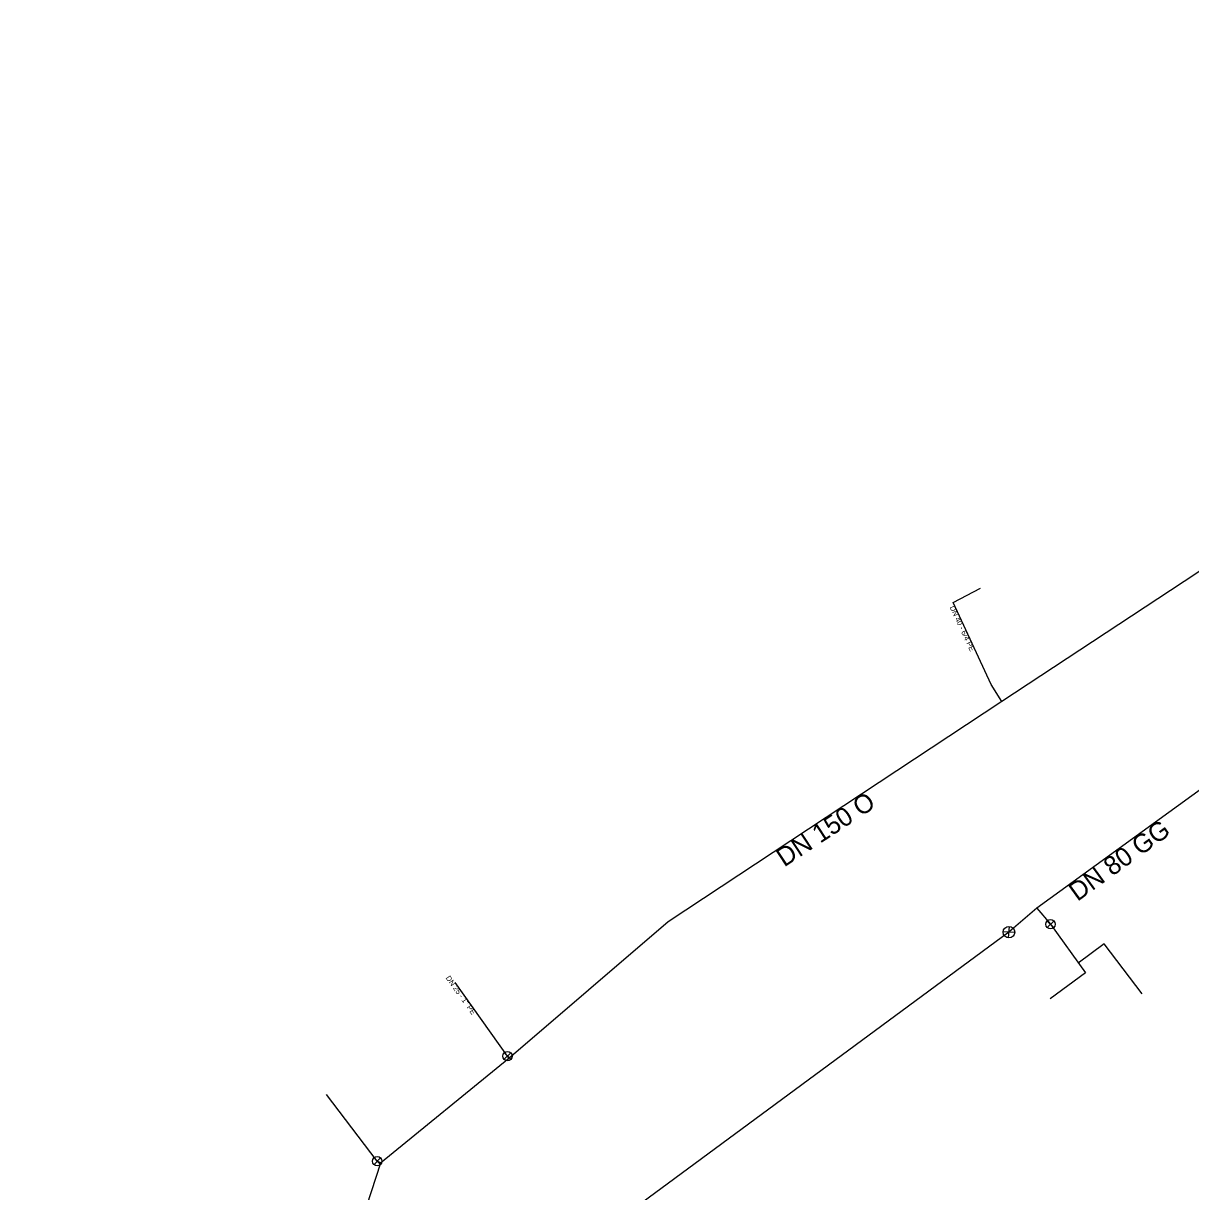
# Model space of a CAD drawing. Extents: x -451501 to -451094, y -1102108 to -1101623.
# Drawn here: x -451475.7 to -451375.4, y -1101738.2 to -1101637.8 of the extents above; entities that cross this region are included whole.
import ezdxf

# ---------------------------------------------------------------- set-up
doc = ezdxf.new("R2010")
doc.units = 0
for name, color, linetype in [('_pripojka_prevzato_z_dokumentace_', 7, 'Continuous'), ('_pripojka_priblizne_', 7, 'Continuous'), ('_voda_smvak_prevzato_z_dokumentace_', 7, 'Continuous'), ('Default', 7, 'Continuous'), ('MoLevel 27', 7, 'Continuous'), ('MoLevel 32', 7, 'Continuous'), ('MoLevel 46', 7, 'Continuous'), ('MoLevel 53', 7, 'Continuous'), ('MoLevel 55', 7, 'Continuous')]:
    doc.layers.add(name, color=color, linetype=linetype)

# ---------------------------------------------------------------- blocks, each defined once
blk = doc.blocks.new('_uzaver_')
at = {"layer": 'Default'}
for p, q in [((-0.000035, -0.000035), (0.000035, 0.000035)), ((0.000035, -0.000035), (-0.000035, 0.000035))]:
    blk.add_line(p, q, dxfattribs=at)
for radius in [0.00005, 0.0000025]:
    blk.add_circle((0, 0), radius, dxfattribs=at)
blk = doc.blocks.new('_uzaver_pripojka_')
at = {"layer": 'Default'}
for p, q in [((-0.000035, -0.000035), (0.000035, 0.000035)), ((0.000035, -0.000035), (-0.000035, 0.000035))]:
    blk.add_line(p, q, dxfattribs=at)
for radius in [0.00005, 0.0000025]:
    blk.add_circle((0, 0), radius, dxfattribs=at)

msp = doc.modelspace()

# ---------------------------------------------------------------- linework, layer by layer
at = {"layer": '_pripojka_prevzato_z_dokumentace_'}
for points in [[(-451388.63, -1101713.82), (-451387.47, -1101715.2), (-451384.47, -1101719.38), (-451387.5, -1101721.61)], [(-451434, -1101726.73), (-451434.13, -1101726.53), (-451438.63, -1101720.2)], [(-451445.03, -1101735.74), (-451445.32, -1101735.57), (-451449.67, -1101729.84)]]:
    msp.add_lwpolyline(points, dxfattribs=at)
at = {"layer": '_pripojka_priblizne_'}
for points in [[(-451391.64, -1101696.06), (-451392.58, -1101694.58), (-451395.84, -1101687.54), (-451393.48, -1101686.3)], [(-451379.58, -1101721.18), (-451382.86, -1101716.87), (-451385.08, -1101718.54)]]:
    msp.add_lwpolyline(points, dxfattribs=at)
at = {"layer": '_voda_smvak_prevzato_z_dokumentace_'}
msp.add_line((-451391.04, -1101715.88), (-451475.73, -1101778.32), dxfattribs=at)
for points in [[(-451287.07, -1101637.76), (-451298.73, -1101646.49), (-451328.51, -1101669.18), (-451365.13, -1101696.77), (-451388.63, -1101713.82), (-451391.04, -1101715.88)], [(-451352.37, -1101668.69), (-451374.89, -1101685.01), (-451391.64, -1101696.06), (-451420.33, -1101714.98), (-451434, -1101726.73), (-451445.03, -1101735.74), (-451449.89, -1101750.62)]]:
    msp.add_lwpolyline(points, dxfattribs=at)

# ---------------------------------------------------------------- block references
at = {"layer": 'MoLevel 27', "xscale": 10000, "yscale": 10000.000000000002, "rotation": 40.52217375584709}
msp.add_blockref('_uzaver_', (-451391.04, -1101715.88), dxfattribs=at)
at = {"layer": 'MoLevel 53', "xscale": 7999.999999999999, "yscale": 7999.999999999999}
for p in [(-451387.47, -1101715.2), (-451434.13, -1101726.53), (-451445.32, -1101735.57)]:
    msp.add_blockref('_uzaver_pripojka_', p, dxfattribs=at)

# ---------------------------------------------------------------- texts
at = {"layer": 'MoLevel 32'}
msp.add_text('DN 40 - 6/4 PE', height=0.455, rotation=294.8138, dxfattribs=at).set_placement((-451396.14, -1101687.95))
at = {"layer": 'MoLevel 46'}
for s, rotation, p in [('DN 150 O', 33.408, (-451410.35, -1101710.32)), ('DN 80 GG', 35.9621, (-451385.15, -1101713.28))]:
    msp.add_text(s, height=1.605, rotation=rotation, dxfattribs=at).set_placement(p)
at = {"layer": 'MoLevel 55'}
msp.add_text("DN 25 - 1'' PE", height=0.455, rotation=305.4216, dxfattribs=at).set_placement((-451439.46, -1101719.82))

doc.saveas('drawing.dxf')
